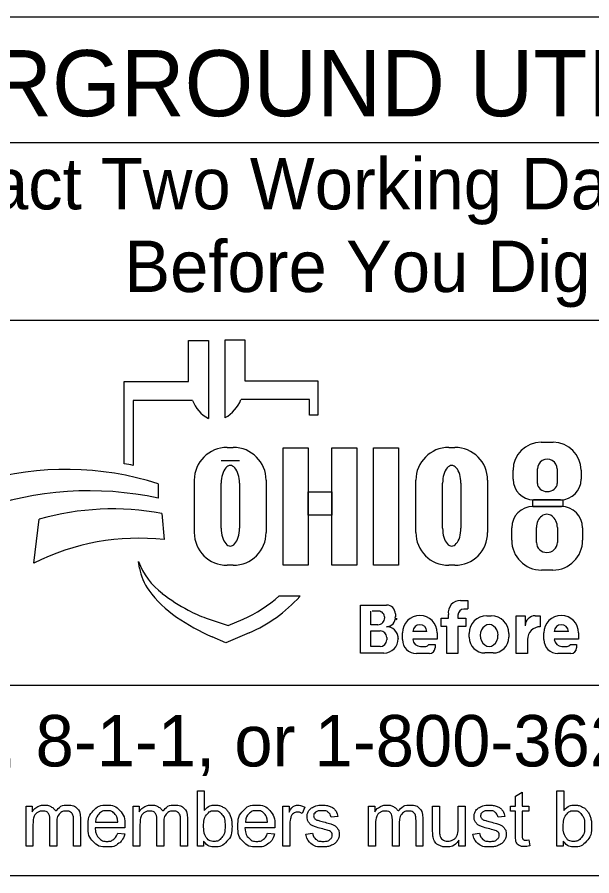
# Model space of a CAD drawing. Extents: x 0 to 42.5, y 0 to 22.
# Drawn here: x 3.267 to 4.831, y 2.143 to 4.48 of the extents above; entities that cross this region are included whole.
import ezdxf

# ---------------------------------------------------------------- set-up
doc = ezdxf.new("R2010")
doc.units = 0
doc.layers.add('SH_Data', color=7, linetype='Continuous')
doc.layers.add('SH_Text', color=7, linetype='Continuous')

msp = doc.modelspace()

# ---------------------------------------------------------------- linework, layer by layer
at = {"layer": 'SH_Data'}
for p, q in [((6.6275, 4.4803), (2.3775, 4.4803)), ((2.3775, 4.1387), (6.6275, 4.1387)), ((2.3775, 3.6553), (6.6275, 3.6553)), ((6.6275, 2.6607), (2.3775, 2.6607)), ((6.6275, 2.1428), (2.3775, 2.1428))]:
    msp.add_line(p, q, dxfattribs=at)
at = {"layer": 'SH_Text'}
for p, q in [((3.7335, 3.4883), (3.7335, 3.5998)), ((3.7335, 3.5998), (3.7872, 3.5998)), ((3.7872, 3.5998), (3.7872, 3.3877)), ((3.8329, 3.39), (3.8329, 3.6021)), ((3.8329, 3.6021), (3.8865, 3.6021)), ((3.8865, 3.6021), (3.8865, 3.4906)), ((3.5576, 3.2644), (3.5576, 3.4883)), ((3.5576, 3.4883), (3.7335, 3.4883)), ((3.8865, 3.4906), (4.0857, 3.4906)), ((4.0857, 3.4906), (4.0857, 3.3968)), ((3.5828, 3.4369), (3.5828, 3.26)), ((3.7439, 3.4369), (3.5828, 3.4369)), ((4.0625, 3.4392), (3.8761, 3.4392)), ((4.0625, 3.3968), (4.0625, 3.4392)), ((4.0857, 3.3968), (4.0625, 3.3968)), ((4.6931, 3.3231), (4.7258, 3.3231)), ((3.8385, 3.3091), (3.8551, 3.3091)), ((4.4416, 3.3091), (4.4581, 3.3091)), ((3.8718, 3.2721), (3.822, 3.2721)), ((4.683, 3.2111), (4.683, 3.2504)), ((4.7371, 3.2504), (4.7371, 3.2111)), ((4.6168, 3.2225), (4.6168, 3.2468)), ((4.8022, 3.2468), (4.8022, 3.2225)), ((3.6509, 3.2097), (3.6509, 3.1709)), ((3.7491, 3.0776), (3.7491, 3.2196)), ((3.822, 3.089), (3.822, 3.2114)), ((3.8718, 3.2114), (3.8718, 3.089)), ((3.9445, 3.2196), (3.9445, 3.0776)), ((4.3521, 3.0776), (4.3521, 3.2196)), ((4.425, 3.089), (4.425, 3.2114)), ((4.4748, 3.2114), (4.4748, 3.089)), ((4.5476, 3.2196), (4.5476, 3.0776)), ((4.7462, 3.1665), (4.6728, 3.1665)), ((4.671, 3.1482), (4.7483, 3.1482)), ((3.312, 2.9936), (3.3267, 3.1137)), ((3.6608, 3.1291), (3.6671, 3.0582)), ((4.6131, 3.0563), (4.6131, 3.0903)), ((4.6806, 3.0503), (4.6806, 3.0912)), ((4.7374, 3.0912), (4.7374, 3.0503)), ((4.8062, 3.0903), (4.8062, 3.0563)), ((3.5997, 2.9807), (3.5967, 2.9986)), ((3.8551, 2.9882), (3.8385, 2.9882)), ((4.4581, 2.9882), (4.4416, 2.9882)), ((4.7252, 2.9753), (4.6941, 2.9753)), ((3.98, 2.9048), (4.0375, 2.9048)), ((4.2013, 2.749), (4.2013, 2.8798)), ((4.2013, 2.8798), (4.2725, 2.8798)), ((4.4739, 2.8926), (4.4934, 2.8926)), ((4.4934, 2.8926), (4.4934, 2.8696)), ((4.2293, 2.8263), (4.2293, 2.8632)), ((4.2545, 2.8632), (4.2332, 2.8632)), ((4.2963, 2.856), (4.2963, 2.8481)), ((4.4406, 2.8442), (4.4406, 2.8546)), ((4.4667, 2.8526), (4.4667, 2.8442)), ((4.4934, 2.8691), (4.4832, 2.8691)), ((3.7816, 2.8444), (3.841, 2.8239)), ((3.841, 2.8239), (3.8821, 2.8417)), ((4.4213, 2.8212), (4.4213, 2.8442)), ((4.4213, 2.8442), (4.4406, 2.8442)), ((4.4667, 2.8442), (4.4883, 2.8442)), ((4.4883, 2.8442), (4.4883, 2.8212)), ((4.5451, 2.8508), (4.5573, 2.8508)), ((4.6254, 2.7478), (4.6254, 2.8505)), ((4.6254, 2.8505), (4.6499, 2.8505)), ((4.6499, 2.8505), (4.6499, 2.8237)), ((4.6772, 2.8505), (4.691, 2.8505)), ((4.691, 2.8505), (4.691, 2.8209)), ((4.2487, 2.8263), (4.2293, 2.8263)), ((4.2293, 2.7669), (4.2293, 2.8097)), ((4.2293, 2.8097), (4.2548, 2.8097)), ((4.3824, 2.8082), (4.3439, 2.8082)), ((4.4362, 2.8212), (4.4213, 2.8212)), ((4.4362, 2.7478), (4.4362, 2.8212)), ((4.4883, 2.8212), (4.4667, 2.8212)), ((4.4667, 2.8212), (4.4667, 2.7478)), ((4.7674, 2.8082), (4.7288, 2.8082)), ((3.835, 2.7769), (3.7976, 2.7934)), ((3.8983, 2.8044), (3.835, 2.7769)), ((4.2729, 2.7916), (4.2729, 2.7853)), ((4.3043, 2.7887), (4.3043, 2.7884)), ((4.3159, 2.7858), (4.3159, 2.8042)), ((4.4104, 2.7866), (4.344, 2.7866)), ((4.4104, 2.8042), (4.4104, 2.7866)), ((4.4973, 2.7922), (4.4973, 2.8029)), ((4.6051, 2.8029), (4.6051, 2.7922)), ((4.6559, 2.786), (4.6559, 2.7478)), ((4.7008, 2.7858), (4.7008, 2.8042)), ((4.7953, 2.7866), (4.7289, 2.7866)), ((4.7953, 2.8042), (4.7953, 2.7866)), ((4.2546, 2.7669), (4.2293, 2.7669)), ((4.3649, 2.7673), (4.379, 2.7673)), ((4.3876, 2.7729), (4.4045, 2.7729)), ((4.4045, 2.7729), (4.4045, 2.7631)), ((4.7498, 2.7673), (4.7639, 2.7673)), ((4.7725, 2.7729), (4.7894, 2.7729)), ((4.7894, 2.7729), (4.7894, 2.7631)), ((4.265, 2.749), (4.2013, 2.749)), ((4.3892, 2.7478), (4.3538, 2.7478)), ((4.4667, 2.7478), (4.4362, 2.7478)), ((4.5623, 2.7494), (4.5401, 2.7494)), ((4.6559, 2.7478), (4.6254, 2.7478)), ((4.7742, 2.7478), (4.7388, 2.7478))]:
    msp.add_line(p, q, dxfattribs=at)
for points in [[(3.991, 3.3081), (4.0589, 3.3081), (4.0589, 2.9881), (3.991, 2.9881)], [(4.1231, 3.3081), (4.1911, 3.3081), (4.1911, 2.9881), (4.1231, 2.9881)], [(4.2364, 3.3081), (4.3052, 3.3081), (4.3052, 2.9881), (4.2364, 2.9881)], [(4.0589, 3.1882), (4.1231, 3.1882), (4.1231, 3.1242), (4.0589, 3.1242)], [(4.6706, 3.1665), (4.7523, 3.1665), (4.7523, 3.1481), (4.6706, 3.1481)]]:
    msp.add_lwpolyline(points, close=True, dxfattribs=at)
for points in [[(3.7743, 2.2239), (3.7573, 2.2239), (3.7573, 2.3741), (3.7757, 2.3741), (3.7757, 2.3206)], [(4.6233, 2.2558), (4.6233, 2.3185), (4.6097, 2.3185), (4.6097, 2.3328), (4.6233, 2.3328), (4.6233, 2.3597), (4.6417, 2.3708), (4.6417, 2.3328), (4.6601, 2.3328), (4.6601, 2.3185), (4.6417, 2.3185), (4.6417, 2.2547)], [(4.7534, 2.2239), (4.7363, 2.2239), (4.7363, 2.3741), (4.7548, 2.3741), (4.7548, 2.3206)], [(3.2912, 2.2239), (3.2912, 2.3328), (3.3077, 2.3328), (3.3077, 2.3174)], [(3.5826, 2.2239), (3.5826, 2.3328), (3.5991, 2.3328), (3.5991, 2.3174)], [(3.9904, 2.2239), (3.9904, 2.3328), (4.007, 2.3328), (4.007, 2.3163)], [(4.0495, 2.3293), (4.043, 2.3122)], [(4.2236, 2.2239), (4.2236, 2.3328), (4.2401, 2.3328), (4.2401, 2.3174)], [(4.3979, 2.2654), (4.3979, 2.3328), (4.4164, 2.3328), (4.4164, 2.2724)], [(4.4676, 2.2745), (4.4676, 2.3328), (4.4861, 2.3328), (4.4861, 2.2239), (4.4696, 2.2239)], [(3.3743, 2.2871), (3.3743, 2.2239), (3.3559, 2.2239), (3.3559, 2.2946)], [(3.4388, 2.2986), (3.4388, 2.2239), (3.4203, 2.2239), (3.4203, 2.2924)], [(3.6657, 2.2871), (3.6657, 2.2239), (3.6473, 2.2239), (3.6473, 2.2946)], [(3.7301, 2.2986), (3.7301, 2.2239), (3.7117, 2.2239), (3.7117, 2.2924)], [(4.1394, 2.3046), (4.1213, 2.3022)], [(4.3067, 2.2871), (4.3067, 2.2239), (4.2883, 2.2239), (4.2883, 2.2946)], [(4.3711, 2.2986), (4.3711, 2.2239), (4.3527, 2.2239), (4.3527, 2.2924)], [(4.594, 2.3046), (4.5759, 2.3022)], [(3.3097, 2.2803), (3.3097, 2.2239), (3.2912, 2.2239)], [(3.56, 2.2736), (3.4788, 2.2736)], [(3.4799, 2.2887), (3.5406, 2.2887)], [(3.601, 2.2803), (3.601, 2.2239), (3.5826, 2.2239)], [(3.968, 2.2736), (3.8868, 2.2736)], [(3.8879, 2.2887), (3.9486, 2.2887)], [(4.0088, 2.2809), (4.0088, 2.2239), (3.9904, 2.2239)], [(4.242, 2.2803), (4.242, 2.2239), (4.2236, 2.2239)], [(3.5404, 2.2591), (3.5595, 2.2567)], [(3.9484, 2.2591), (3.9675, 2.2567)], [(4.053, 2.2564), (4.0712, 2.2593)], [(4.5076, 2.2564), (4.5258, 2.2593)], [(3.7743, 2.2375), (3.7743, 2.2239)], [(4.4696, 2.2239), (4.4696, 2.24)], [(4.6601, 2.2404), (4.6628, 2.2241)], [(4.7534, 2.2375), (4.7534, 2.2239)]]:
    msp.add_lwpolyline(points, dxfattribs=at)
for centre, radius, start, end in [((3.8353, 3.4736), 0.0985, 201.9296, 240.7469), ((3.7847, 3.476), 0.0985, 299.2531, 338.0704), ((4.6931, 3.2468), 0.0763, 90, 180), ((4.7258, 3.2468), 0.0763, 0, 90), ((3.8385, 3.2196), 0.0895, 90, 180), ((3.8551, 3.2196), 0.0895, 0, 90), ((4.4416, 3.2196), 0.0895, 90, 180), ((4.4581, 3.2196), 0.0895, 0, 90), ((3.3997, 2.4302), 0.8191, 72.1402, 106.3144), ((3.4295, 2.4554), 0.8191, 79.2074, 81.0007), ((4.6728, 3.2225), 0.056, 180, 270), ((4.7462, 3.2225), 0.056, 270, 0), ((3.4628, 2.2991), 0.8919, 77.8238, 109.8274), ((3.5267, 2.4094), 0.7322, 79.44, 105.8467), ((4.671, 3.0903), 0.0579, 90, 180), ((4.7483, 3.0903), 0.0579, 0, 90), ((3.8385, 3.0776), 0.0895, 180, 270), ((3.8551, 3.0776), 0.0895, 270, 0), ((4.4416, 3.0776), 0.0895, 180, 270), ((4.4581, 3.0776), 0.0895, 270, 0), ((3.5987, 2.4262), 0.6357, 83.8248, 116.8021), ((4.6941, 3.0563), 0.081, 180, 270), ((4.7252, 3.0563), 0.081, 270, 0), ((3.7841, 3.0707), 0.2008, 201.0457, 232.5314), ((3.741, 3.0048), 0.1433, 189.6817, 216.0884), ((3.8747, 3.1022), 0.3088, 216.0884, 235.7167), ((3.9766, 3.3219), 0.5173, 232.5314, 241.794), ((3.7387, 3.1722), 0.3602, 293.4582, 312.0712), ((3.7387, 3.1722), 0.401, 293.4582, 317.8286), ((4.2725, 2.856), 0.0238, 0, 90), ((4.4739, 2.859), 0.0335, 90, 187.5187), ((3.8914, 3.1631), 0.3371, 241.794, 250.9821), ((4.2505, 2.8463), 0.0169, 357.8325, 90), ((4.4832, 2.8526), 0.0165, 90, 180), ((4.0412, 3.3465), 0.6044, 235.7167, 246.2325), ((4.2487, 2.845), 0.0187, 270, 2.0582), ((4.2721, 2.8453), 0.0243, 270, 6.6529), ((4.2827, 2.8438), 0.0175, 347.4023, 0), ((4.3631, 2.8042), 0.0473, 0, 180), ((4.5451, 2.8029), 0.0478, 90, 180), ((4.5573, 2.8029), 0.0478, 0, 90), ((4.6768, 2.8237), 0.0269, 89.2449, 180), ((4.7481, 2.8042), 0.0473, 0, 180), ((4.2548, 2.7916), 0.0181, 0, 90), ((4.2722, 2.7889), 0.0321, 4.0748, 90), ((4.3632, 2.8072), 0.0193, 2.9632, 177.0368), ((4.6908, 2.786), 0.0349, 89.6033, 180), ((4.7481, 2.8072), 0.0193, 2.9632, 177.0368), ((4.2546, 2.7853), 0.0184, 270, 0), ((4.265, 2.7884), 0.0393, 270, 0), ((4.2714, 2.7887), 0.033, 0, 11.7502), ((4.3538, 2.7858), 0.038, 180, 270), ((4.3649, 2.7883), 0.021, 184.827, 270), ((4.5401, 2.7922), 0.0428, 180, 270), ((4.5623, 2.7922), 0.0428, 270, 0), ((4.7388, 2.7858), 0.038, 180, 270), ((4.7498, 2.7883), 0.021, 184.827, 270), ((4.379, 2.7767), 0.00938, 270, 335.9979), ((4.3892, 2.7631), 0.0152, 270, 0), ((4.7639, 2.7767), 0.00938, 270, 335.9979), ((4.7742, 2.7631), 0.0152, 270, 0)]:
    msp.add_arc(centre, radius, start, end, dxfattribs=at)
for centre, major_axis, ratio, start_param, end_param in [((4.71, 3.2504), (0.0271, 0), 0.969373, 0, 3.141593), ((3.8469, 3.2114), (0, 0.0484), 0.514403, 4.712389, 7.853982), ((4.4499, 3.2114), (0, 0.0484), 0.514403, 4.712389, 7.853982), ((4.71, 3.2111), (0.0271, 0), 0.818453, 3.141593, 6.283185), ((4.709, 3.0912), (0, 0.0358), 0.794529, 4.712389, 7.853982), ((3.8469, 3.089), (0, 0.0484), 0.514403, 1.570796, 4.712389), ((4.4499, 3.089), (0, 0.0484), 0.514403, 1.570796, 4.712389), ((4.709, 3.0503), (0.0284, 0), 0.959837, 3.141593, 6.283185), ((4.5517, 2.7976), (0, 0.029), 0.832186, 4.712389, 7.853982), ((4.5517, 2.7976), (0, 0.0302), 0.797287, 1.570796, 4.712389)]:
    msp.add_ellipse(centre, major_axis=major_axis, ratio=ratio, start_param=start_param, end_param=end_param, dxfattribs=at)
for points in [[(3.3077, 2.3174), (3.3128, 2.3254), (3.3214, 2.3303), (3.3299, 2.3352), (3.3407, 2.3352), (3.3528, 2.3352), (3.3606, 2.3301), (3.3683, 2.3251), (3.3715, 2.3161), (3.3844, 2.3352), (3.4051, 2.3352), (3.4213, 2.3352), (3.43, 2.3262), (3.4388, 2.3172), (3.4388, 2.2986)], [(3.3559, 2.2946), (3.3559, 2.3069), (3.3514, 2.313), (3.3469, 2.3191), (3.3366, 2.3191), (3.3288, 2.3191), (3.3222, 2.315), (3.3156, 2.311), (3.3126, 2.3031), (3.3097, 2.2952), (3.3097, 2.2803)], [(3.4203, 2.2924), (3.4203, 2.3035), (3.4185, 2.3083), (3.4168, 2.3132), (3.412, 2.3162), (3.4073, 2.3191), (3.401, 2.3191), (3.3895, 2.3191), (3.3819, 2.3115), (3.3743, 2.3039), (3.3743, 2.2871)], [(3.5595, 2.2567), (3.555, 2.24), (3.5428, 2.2307), (3.5306, 2.2215), (3.5117, 2.2215), (3.4878, 2.2215), (3.4738, 2.2362), (3.4598, 2.2509), (3.4598, 2.2774), (3.4598, 2.3049), (3.474, 2.32), (3.4881, 2.3352), (3.5106, 2.3352), (3.5324, 2.3352), (3.5463, 2.3203), (3.5601, 2.3055), (3.5601, 2.2785), (3.5601, 2.2769), (3.56, 2.2736)], [(3.5406, 2.2887), (3.5394, 2.3025), (3.5337, 2.3094), (3.5249, 2.3201), (3.5108, 2.3201), (3.4981, 2.3201), (3.4894, 2.3115), (3.4808, 2.303), (3.4799, 2.2887)], [(3.5991, 2.3174), (3.6042, 2.3254), (3.6127, 2.3303), (3.6212, 2.3352), (3.6321, 2.3352), (3.6442, 2.3352), (3.6519, 2.3301), (3.6597, 2.3251), (3.6628, 2.3161), (3.6758, 2.3352), (3.6965, 2.3352), (3.7127, 2.3352), (3.7214, 2.3262), (3.7301, 2.3172), (3.7301, 2.2986)], [(3.6473, 2.2946), (3.6473, 2.3069), (3.6428, 2.313), (3.6383, 2.3191), (3.628, 2.3191), (3.6202, 2.3191), (3.6136, 2.315), (3.607, 2.311), (3.604, 2.3031), (3.601, 2.2952), (3.601, 2.2803)], [(3.7117, 2.2924), (3.7117, 2.3035), (3.7099, 2.3083), (3.7081, 2.3132), (3.7034, 2.3162), (3.6987, 2.3191), (3.6923, 2.3191), (3.6809, 2.3191), (3.6733, 2.3115), (3.6657, 2.3039), (3.6657, 2.2871)], [(3.7741, 2.2792), (3.7741, 2.2596), (3.7794, 2.2509), (3.7881, 2.2366), (3.8029, 2.2366), (3.815, 2.2366), (3.8238, 2.2471), (3.8326, 2.2576), (3.8326, 2.2784), (3.8326, 2.2998), (3.8241, 2.3099), (3.8157, 2.3201), (3.8038, 2.3201), (3.7917, 2.3201), (3.7829, 2.3096), (3.7741, 2.299), (3.7741, 2.2792)], [(3.7757, 2.3206), (3.7874, 2.3352), (3.8055, 2.3352), (3.8155, 2.3352), (3.8245, 2.3311), (3.8335, 2.3271), (3.8392, 2.3198), (3.845, 2.3124), (3.8483, 2.3021), (3.8516, 2.2918), (3.8516, 2.28), (3.8516, 2.252), (3.8378, 2.2368), (3.8239, 2.2215), (3.8046, 2.2215), (3.7853, 2.2215), (3.7743, 2.2375)], [(3.9675, 2.2567), (3.963, 2.24), (3.9508, 2.2307), (3.9386, 2.2215), (3.9196, 2.2215), (3.8958, 2.2215), (3.8818, 2.2362), (3.8678, 2.2509), (3.8678, 2.2774), (3.8678, 2.3049), (3.882, 2.32), (3.8961, 2.3352), (3.9186, 2.3352), (3.9404, 2.3352), (3.9543, 2.3203), (3.9681, 2.3055), (3.9681, 2.2785), (3.9681, 2.2769), (3.968, 2.2736)], [(3.9486, 2.2887), (3.9474, 2.3025), (3.9417, 2.3094), (3.9328, 2.3201), (3.9188, 2.3201), (3.9061, 2.3201), (3.8974, 2.3115), (3.8888, 2.303), (3.8879, 2.2887)], [(4.007, 2.3163), (4.0133, 2.3278), (4.0187, 2.3315), (4.0241, 2.3352), (4.0305, 2.3352), (4.0398, 2.3352), (4.0495, 2.3293)], [(4.043, 2.3122), (4.0363, 2.3162), (4.0295, 2.3162), (4.0235, 2.3162), (4.0187, 2.3125), (4.0139, 2.3089), (4.0119, 2.3024), (4.0088, 2.2926), (4.0088, 2.2809)], [(4.1213, 2.3022), (4.1201, 2.3106), (4.1142, 2.3153), (4.1083, 2.3201), (4.0975, 2.3201), (4.0848, 2.3201), (4.0794, 2.3159), (4.0739, 2.3116), (4.0739, 2.306), (4.0739, 2.3024), (4.0762, 2.2995), (4.0785, 2.2966), (4.0833, 2.2946), (4.086, 2.2936), (4.0996, 2.2899), (4.1192, 2.2847), (4.1269, 2.2813), (4.1347, 2.278), (4.1391, 2.2717), (4.1435, 2.2653), (4.1435, 2.2559), (4.1435, 2.2467), (4.1381, 2.2386), (4.1327, 2.2304), (4.1226, 2.226), (4.1124, 2.2215), (4.0996, 2.2215), (4.0784, 2.2215), (4.0672, 2.2303), (4.0561, 2.2391), (4.053, 2.2564)], [(4.0712, 2.2593), (4.0727, 2.2483), (4.0798, 2.2425), (4.0868, 2.2366), (4.0995, 2.2366), (4.1122, 2.2366), (4.1184, 2.2418), (4.1245, 2.247), (4.1245, 2.254), (4.1245, 2.2602), (4.1191, 2.2638), (4.1153, 2.2663), (4.1002, 2.2701), (4.0799, 2.2752), (4.072, 2.2789), (4.0642, 2.2827), (4.0601, 2.2893), (4.0561, 2.2959), (4.0561, 2.3038), (4.0561, 2.3111), (4.0594, 2.3173), (4.0628, 2.3235), (4.0685, 2.3276), (4.0728, 2.3308), (4.0803, 2.333), (4.0877, 2.3352), (4.0962, 2.3352), (4.109, 2.3352), (4.1187, 2.3315), (4.1284, 2.3278), (4.133, 2.3215), (4.1377, 2.3152), (4.1394, 2.3046)], [(4.2401, 2.3174), (4.2452, 2.3254), (4.2537, 2.3303), (4.2622, 2.3352), (4.2731, 2.3352), (4.2852, 2.3352), (4.2929, 2.3301), (4.3007, 2.3251), (4.3038, 2.3161), (4.3168, 2.3352), (4.3375, 2.3352), (4.3537, 2.3352), (4.3624, 2.3262), (4.3711, 2.3172), (4.3711, 2.2986)], [(4.2883, 2.2946), (4.2883, 2.3069), (4.2838, 2.313), (4.2793, 2.3191), (4.269, 2.3191), (4.2612, 2.3191), (4.2546, 2.315), (4.248, 2.311), (4.245, 2.3031), (4.242, 2.2952), (4.242, 2.2803)], [(4.3527, 2.2924), (4.3527, 2.3035), (4.3509, 2.3083), (4.3491, 2.3132), (4.3444, 2.3162), (4.3397, 2.3191), (4.3333, 2.3191), (4.3219, 2.3191), (4.3143, 2.3115), (4.3067, 2.3039), (4.3067, 2.2871)], [(4.5759, 2.3022), (4.5747, 2.3106), (4.5688, 2.3153), (4.5629, 2.3201), (4.5521, 2.3201), (4.5394, 2.3201), (4.5339, 2.3159), (4.5285, 2.3116), (4.5285, 2.306), (4.5285, 2.3024), (4.5308, 2.2995), (4.533, 2.2966), (4.5378, 2.2946), (4.5406, 2.2936), (4.5542, 2.2899), (4.5737, 2.2847), (4.5815, 2.2813), (4.5893, 2.278), (4.5937, 2.2717), (4.5981, 2.2653), (4.5981, 2.2559), (4.5981, 2.2467), (4.5927, 2.2386), (4.5873, 2.2304), (4.5772, 2.226), (4.567, 2.2215), (4.5542, 2.2215), (4.5329, 2.2215), (4.5218, 2.2303), (4.5107, 2.2391), (4.5076, 2.2564)], [(4.5258, 2.2593), (4.5273, 2.2483), (4.5343, 2.2425), (4.5414, 2.2366), (4.554, 2.2366), (4.5668, 2.2366), (4.5729, 2.2418), (4.5791, 2.247), (4.5791, 2.254), (4.5791, 2.2602), (4.5736, 2.2638), (4.5698, 2.2663), (4.5548, 2.2701), (4.5345, 2.2752), (4.5266, 2.2789), (4.5188, 2.2827), (4.5147, 2.2893), (4.5107, 2.2959), (4.5107, 2.3038), (4.5107, 2.3111), (4.514, 2.3173), (4.5173, 2.3235), (4.5231, 2.3276), (4.5274, 2.3308), (4.5348, 2.333), (4.5423, 2.3352), (4.5508, 2.3352), (4.5636, 2.3352), (4.5733, 2.3315), (4.583, 2.3278), (4.5876, 2.3215), (4.5922, 2.3152), (4.594, 2.3046)], [(4.7532, 2.2792), (4.7532, 2.2596), (4.7585, 2.2509), (4.7672, 2.2366), (4.782, 2.2366), (4.7941, 2.2366), (4.8029, 2.2471), (4.8116, 2.2576), (4.8116, 2.2784), (4.8116, 2.2998), (4.8032, 2.3099), (4.7948, 2.3201), (4.7828, 2.3201), (4.7708, 2.3201), (4.762, 2.3096), (4.7532, 2.299), (4.7532, 2.2792)], [(4.7548, 2.3206), (4.7664, 2.3352), (4.7846, 2.3352), (4.7946, 2.3352), (4.8036, 2.3311), (4.8125, 2.3271), (4.8183, 2.3198), (4.8241, 2.3124), (4.8274, 2.3021), (4.8306, 2.2918), (4.8306, 2.28), (4.8306, 2.252), (4.8168, 2.2368), (4.803, 2.2215), (4.7836, 2.2215), (4.7644, 2.2215), (4.7534, 2.2375)], [(3.4788, 2.2736), (3.4799, 2.2557), (3.489, 2.2462), (3.4981, 2.2366), (3.5117, 2.2366), (3.5219, 2.2366), (3.5291, 2.242), (3.5362, 2.2473), (3.5404, 2.2591)], [(3.8868, 2.2736), (3.8879, 2.2557), (3.897, 2.2462), (3.9061, 2.2366), (3.9197, 2.2366), (3.9299, 2.2366), (3.937, 2.242), (3.9442, 2.2473), (3.9484, 2.2591)], [(4.4164, 2.2724), (4.4164, 2.258), (4.4175, 2.253), (4.4192, 2.2457), (4.4249, 2.2416), (4.4305, 2.2374), (4.4388, 2.2374), (4.4471, 2.2374), (4.4543, 2.2417), (4.4616, 2.2459), (4.4646, 2.2533), (4.4676, 2.2606), (4.4676, 2.2745)], [(4.4696, 2.24), (4.4569, 2.2215), (4.4351, 2.2215), (4.4255, 2.2215), (4.4171, 2.2252), (4.4088, 2.2289), (4.4047, 2.2345), (4.4007, 2.2401), (4.3991, 2.2482), (4.3979, 2.2536), (4.3979, 2.2654)], [(4.6628, 2.2241), (4.655, 2.2224), (4.6488, 2.2224), (4.6388, 2.2224), (4.6333, 2.2256), (4.6278, 2.2288), (4.6255, 2.234), (4.6233, 2.2392), (4.6233, 2.2558)], [(4.6417, 2.2547), (4.6417, 2.2468), (4.6427, 2.2445), (4.6436, 2.2423), (4.6458, 2.2409), (4.648, 2.2396), (4.6521, 2.2396), (4.6551, 2.2396), (4.6601, 2.2404)]]:
    msp.add_open_spline(points, degree=3, dxfattribs=at)

# ---------------------------------------------------------------- texts
for s, height, p in [('UNDERGROUND UTILITIES', 0.18, (2.5057, 4.2106)), ('Contact Two Working Days', 0.14, (2.7972, 3.9571)), ('Before You Dig', 0.14, (3.5583, 3.7321)), ('OHIO811, 8-1-1, or 1-800-362-2764', 0.14, (2.422, 2.4406))]:
    msp.add_text(s, height=height, dxfattribs=at).set_placement(p)

doc.saveas('drawing.dxf')
